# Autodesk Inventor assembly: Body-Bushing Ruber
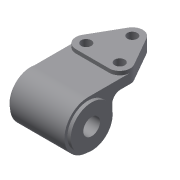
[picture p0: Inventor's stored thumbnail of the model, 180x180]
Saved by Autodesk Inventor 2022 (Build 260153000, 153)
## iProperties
Created: 2011-07
Part Number: Body-Bushing Ruber
Document SubType Name: Assembly
Designer: CadCim
Author: CadCim
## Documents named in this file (3)
- D:\PROJECTS_2021\Resources\Tutorial Files\c09_Inv_2022_tut\c09_Inv_2022_tut\c09_Inv_tut_2022\c09_tut03_inv\Anti Vibration Mount\Body-Bushing Ruber.iam
- D:\PROJECTS_2021\Resources\Tutorial Files\c09_Inv_2022_tut\c09_Inv_2022_tut\c09_Inv_tut_2022\c09_tut03_inv\Anti Vibration Mount\Body.ipt
- D:\PROJECTS_2021\Resources\Tutorial Files\c09_Inv_2022_tut\c09_Inv_2022_tut\c09_Inv_tut_2022\c09_tut03_inv\Anti Vibration Mount\Bushing Rubber.ipt
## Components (3 placed, 2 different names)
1. Body:1 — Insert:1, Insert:2
2. Bushing Rubber:1 — Insert:1
3. Bushing Rubber:2 — Insert:2
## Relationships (2: Insert 2)
- Insert:1: Body:1 ↔ Bushing Rubber:1
- Insert:2: Body:1 ↔ Bushing Rubber:2
